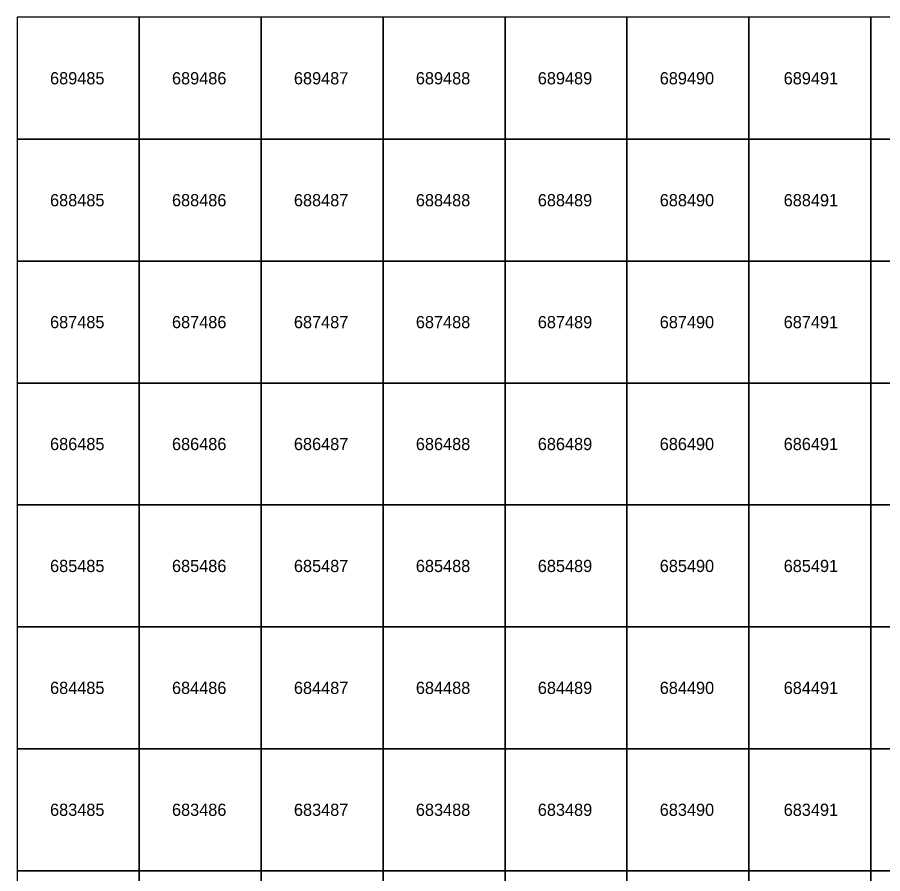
# Model space of a CAD drawing. Extents: x 25485000 to 25520000, y 6656775 to 6690000.
# Drawn here: x 25485000 to 25492097, y 6682976 to 6690000 of the extents above; entities that cross this region are included whole.
import ezdxf

# ---------------------------------------------------------------- set-up
doc = ezdxf.new("R2010")
doc.units = 0
doc.layers.add('Level 63', color=7, linetype='Continuous')

msp = doc.modelspace()

# ---------------------------------------------------------------- linework, layer by layer
at = {"layer": 'Level 63'}
for points in [[(25485000, 6689000), (25486000, 6689000), (25486000, 6690000), (25485000, 6690000)], [(25486000, 6689000), (25487000, 6689000), (25487000, 6690000), (25486000, 6690000)], [(25487000, 6689000), (25488000, 6689000), (25488000, 6690000), (25487000, 6690000)], [(25488000, 6689000), (25489000, 6689000), (25489000, 6690000), (25488000, 6690000)], [(25489000, 6689000), (25490000, 6689000), (25490000, 6690000), (25489000, 6690000)], [(25490000, 6689000), (25491000, 6689000), (25491000, 6690000), (25490000, 6690000)], [(25491000, 6689000), (25492000, 6689000), (25492000, 6690000), (25491000, 6690000)], [(25492000, 6689000), (25493000, 6689000), (25493000, 6690000), (25492000, 6690000)], [(25485000, 6688000), (25486000, 6688000), (25486000, 6689000), (25485000, 6689000)], [(25486000, 6688000), (25487000, 6688000), (25487000, 6689000), (25486000, 6689000)], [(25487000, 6688000), (25488000, 6688000), (25488000, 6689000), (25487000, 6689000)], [(25488000, 6688000), (25489000, 6688000), (25489000, 6689000), (25488000, 6689000)], [(25489000, 6688000), (25490000, 6688000), (25490000, 6689000), (25489000, 6689000)], [(25490000, 6688000), (25491000, 6688000), (25491000, 6689000), (25490000, 6689000)], [(25491000, 6688000), (25492000, 6688000), (25492000, 6689000), (25491000, 6689000)], [(25492000, 6688000), (25493000, 6688000), (25493000, 6689000), (25492000, 6689000)], [(25485000, 6687000), (25486000, 6687000), (25486000, 6688000), (25485000, 6688000)], [(25486000, 6687000), (25487000, 6687000), (25487000, 6688000), (25486000, 6688000)], [(25487000, 6687000), (25488000, 6687000), (25488000, 6688000), (25487000, 6688000)], [(25488000, 6687000), (25489000, 6687000), (25489000, 6688000), (25488000, 6688000)], [(25489000, 6687000), (25490000, 6687000), (25490000, 6688000), (25489000, 6688000)], [(25490000, 6687000), (25491000, 6687000), (25491000, 6688000), (25490000, 6688000)], [(25491000, 6687000), (25492000, 6687000), (25492000, 6688000), (25491000, 6688000)], [(25492000, 6687000), (25493000, 6687000), (25493000, 6688000), (25492000, 6688000)], [(25485000, 6686000), (25486000, 6686000), (25486000, 6687000), (25485000, 6687000)], [(25486000, 6686000), (25487000, 6686000), (25487000, 6687000), (25486000, 6687000)], [(25487000, 6686000), (25488000, 6686000), (25488000, 6687000), (25487000, 6687000)], [(25488000, 6686000), (25489000, 6686000), (25489000, 6687000), (25488000, 6687000)], [(25489000, 6686000), (25490000, 6686000), (25490000, 6687000), (25489000, 6687000)], [(25490000, 6686000), (25491000, 6686000), (25491000, 6687000), (25490000, 6687000)], [(25491000, 6686000), (25492000, 6686000), (25492000, 6687000), (25491000, 6687000)], [(25492000, 6686000), (25493000, 6686000), (25493000, 6687000), (25492000, 6687000)], [(25485000, 6685000), (25486000, 6685000), (25486000, 6686000), (25485000, 6686000)], [(25486000, 6685000), (25487000, 6685000), (25487000, 6686000), (25486000, 6686000)], [(25487000, 6685000), (25488000, 6685000), (25488000, 6686000), (25487000, 6686000)], [(25488000, 6685000), (25489000, 6685000), (25489000, 6686000), (25488000, 6686000)], [(25489000, 6685000), (25490000, 6685000), (25490000, 6686000), (25489000, 6686000)], [(25490000, 6685000), (25491000, 6685000), (25491000, 6686000), (25490000, 6686000)], [(25491000, 6685000), (25492000, 6685000), (25492000, 6686000), (25491000, 6686000)], [(25492000, 6685000), (25493000, 6685000), (25493000, 6686000), (25492000, 6686000)], [(25485000, 6684000), (25486000, 6684000), (25486000, 6685000), (25485000, 6685000)], [(25486000, 6684000), (25487000, 6684000), (25487000, 6685000), (25486000, 6685000)], [(25487000, 6684000), (25488000, 6684000), (25488000, 6685000), (25487000, 6685000)], [(25488000, 6684000), (25489000, 6684000), (25489000, 6685000), (25488000, 6685000)], [(25489000, 6684000), (25490000, 6684000), (25490000, 6685000), (25489000, 6685000)], [(25490000, 6684000), (25491000, 6684000), (25491000, 6685000), (25490000, 6685000)], [(25491000, 6684000), (25492000, 6684000), (25492000, 6685000), (25491000, 6685000)], [(25492000, 6684000), (25493000, 6684000), (25493000, 6685000), (25492000, 6685000)], [(25485000, 6683000), (25486000, 6683000), (25486000, 6684000), (25485000, 6684000)], [(25486000, 6683000), (25487000, 6683000), (25487000, 6684000), (25486000, 6684000)], [(25487000, 6683000), (25488000, 6683000), (25488000, 6684000), (25487000, 6684000)], [(25488000, 6683000), (25489000, 6683000), (25489000, 6684000), (25488000, 6684000)], [(25489000, 6683000), (25490000, 6683000), (25490000, 6684000), (25489000, 6684000)], [(25490000, 6683000), (25491000, 6683000), (25491000, 6684000), (25490000, 6684000)], [(25491000, 6683000), (25492000, 6683000), (25492000, 6684000), (25491000, 6684000)], [(25492000, 6683000), (25493000, 6683000), (25493000, 6684000), (25492000, 6684000)], [(25485000, 6682000), (25486000, 6682000), (25486000, 6683000), (25485000, 6683000)], [(25486000, 6682000), (25487000, 6682000), (25487000, 6683000), (25486000, 6683000)], [(25487000, 6682000), (25488000, 6682000), (25488000, 6683000), (25487000, 6683000)], [(25488000, 6682000), (25489000, 6682000), (25489000, 6683000), (25488000, 6683000)], [(25489000, 6682000), (25490000, 6682000), (25490000, 6683000), (25489000, 6683000)], [(25490000, 6682000), (25491000, 6682000), (25491000, 6683000), (25490000, 6683000)], [(25491000, 6682000), (25492000, 6682000), (25492000, 6683000), (25491000, 6683000)], [(25492000, 6682000), (25493000, 6682000), (25493000, 6683000), (25492000, 6683000)]]:
    msp.add_lwpolyline(points, close=True, dxfattribs=at)

# ---------------------------------------------------------------- texts
for s, p in [('689485', (25485268.5, 6689450)), ('689486', (25486268.5, 6689450)), ('689487', (25487268.5, 6689450)), ('689488', (25488268.5, 6689450)), ('689489', (25489268.5, 6689450)), ('689490', (25490268.5, 6689450)), ('689491', (25491285.1, 6689450)), ('688485', (25485268.5, 6688450)), ('688486', (25486268.5, 6688450)), ('688487', (25487268.5, 6688450)), ('688488', (25488268.5, 6688450)), ('688489', (25489268.5, 6688450)), ('688490', (25490268.5, 6688450)), ('688491', (25491285.1, 6688450)), ('687485', (25485268.5, 6687450)), ('687486', (25486268.5, 6687450)), ('687487', (25487268.5, 6687450)), ('687488', (25488268.5, 6687450)), ('687489', (25489268.5, 6687450)), ('687490', (25490268.5, 6687450)), ('687491', (25491285.1, 6687450)), ('686485', (25485268.5, 6686450)), ('686486', (25486268.5, 6686450)), ('686487', (25487268.5, 6686450)), ('686488', (25488268.5, 6686450)), ('686489', (25489268.5, 6686450)), ('686490', (25490268.5, 6686450)), ('686491', (25491285.1, 6686450)), ('685485', (25485268.5, 6685450)), ('685486', (25486268.5, 6685450)), ('685487', (25487268.5, 6685450)), ('685488', (25488268.5, 6685450)), ('685489', (25489268.5, 6685450)), ('685490', (25490268.5, 6685450)), ('685491', (25491285.1, 6685450)), ('684485', (25485268.5, 6684450)), ('684486', (25486268.5, 6684450)), ('684487', (25487268.5, 6684450)), ('684488', (25488268.5, 6684450)), ('684489', (25489268.5, 6684450)), ('684490', (25490268.5, 6684450)), ('684491', (25491285.1, 6684450)), ('683485', (25485268.5, 6683450)), ('683486', (25486268.5, 6683450)), ('683487', (25487268.5, 6683450)), ('683488', (25488268.5, 6683450)), ('683489', (25489268.5, 6683450)), ('683490', (25490268.5, 6683450)), ('683491', (25491285.1, 6683450))]:
    msp.add_text(s, height=100, dxfattribs=at).set_placement(p)

doc.saveas('drawing.dxf')
